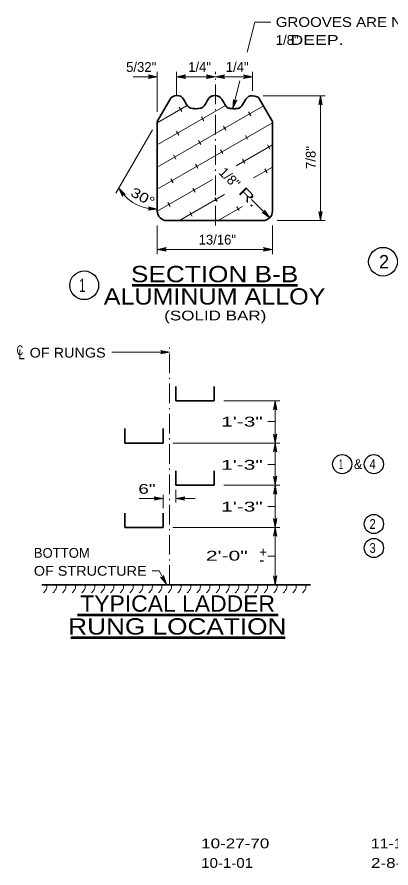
# Model space of a CAD drawing. Extents: x 16 to 133, y -56 to 112.
# Drawn here: x 16.4 to 55.4, y -51.9 to 36.9 of the extents above; entities that cross this region are included whole.
import ezdxf
from ezdxf.enums import TextEntityAlignment as Align

# ---------------------------------------------------------------- set-up
doc = ezdxf.new("R2010")
doc.units = 0
doc.header["$LTSCALE"] = 0.41
doc.linetypes.add('DOT_DASHED', pattern=[7.7, 5, -1.2, 0.3, -1.2])
for name, color, linetype, lineweight in [('1', 7, 'Continuous', 35), ('10', 7, 'Continuous', 13), ('12', 7, 'Continuous', 53), ('13', 7, 'Continuous', 25), ('6', 7, 'Continuous', 13)]:
    doc.layers.add(name, color=color, linetype=linetype, lineweight=lineweight)

msp = doc.modelspace()

# ---------------------------------------------------------------- linework, layer by layer
at = {"layer": '1'}
for p, q in [((31.0095, 25.9659), (32.4539, 28.4677)), ((43.0095, 25.9659), (41.5657, 28.4667)), ((31.0095, 25.9659), (31.0095, 16.6326)), ((43.0095, 16.6326), (43.0095, 25.9659)), ((32.0095, 15.6326), (42.0095, 15.6326)), ((32.9448, -3.1687), (32.9448, -1.6687)), ((36.9448, -3.1687), (36.9448, -1.6687)), ((32.9448, -3.1687), (36.9448, -3.1687)), ((27.6115, -7.5687), (27.6115, -6.0687)), ((31.6115, -7.5687), (31.6115, -6.0687)), ((27.6115, -7.5687), (31.6115, -7.5687)), ((32.9448, -11.9687), (32.9448, -10.4687)), ((36.9448, -11.9687), (36.9448, -10.4687)), ((32.9448, -11.9687), (36.9448, -11.9687)), ((27.6115, -16.3687), (27.6115, -14.8687)), ((31.6115, -16.3687), (31.6115, -14.8687)), ((27.6115, -16.3687), (31.6115, -16.3687)), ((18.9686, -22.3687), (46.9686, -22.3687))]:
    msp.add_line(p, q, dxfattribs=at)
for centre, start, end in [((32.0095, 16.6326), 180, 270), ((42.0095, 16.6326), 270, 0)]:
    msp.add_arc(centre, 1, start, end, dxfattribs=at)
for points in [[(32.4379, 28.4576), (32.5856, 28.55), (33.4826, 28.5571), (34.4532, 27.37), (34.6601, 27.3272), (35.0233, 27.2992)], [(37.6093, 28.4576), (37.4615, 28.55), (36.5646, 28.5571), (35.5939, 27.37), (35.3384, 27.3253), (35.0233, 27.2992)], [(36.413, 28.4576), (36.5608, 28.55), (37.4577, 28.5571), (38.4284, 27.37), (38.5783, 27.3312), (39.0133, 27.2992)], [(41.5656, 28.4666), (41.4018, 28.55), (40.5048, 28.5571), (39.5342, 27.37), (39.4171, 27.336), (39.0133, 27.2992)]]:
    msp.add_spline(points, degree=3, dxfattribs=at)
at = {"layer": '10'}
for p, q in [((31.0095, 26.9659), (31.0095, 31.1415)), ((33.0246, 28.6541), (33.0246, 31.1415)), ((40.9393, 29.1615), (40.9393, 31.1415)), ((28.5095, 30.6415), (31.0095, 30.6415)), ((33.0246, 30.6415), (40.9393, 30.6415)), ((39.6202, 30.2011), (38.8935, 27.3247)), ((42.0421, 28.6415), (48.5095, 28.6415)), ((48.0095, 15.6326), (48.0095, 28.6415)), ((26.6995, 18.5007), (30.5095, 25.0999)), ((42.7166, 15.9255), (40.8158, 17.8263)), ((31.0095, 15.1326), (31.0095, 12.1326)), ((43.0095, 15.1326), (43.0095, 12.1326)), ((43.5095, 15.6326), (48.5095, 15.6326)), ((31.0095, 12.6326), (43.0095, 12.6326)), ((32.2782, 1.91), (26.2782, 1.91)), ((37.9448, -3.1687), (43.7782, -3.1687)), ((43.2782, -22.3687), (43.2782, -3.1687)), ((43.2782, -5.3199), (42.5282, -5.3199)), ((32.6115, -7.5687), (43.7782, -7.5687)), ((43.2782, -9.808), (42.5282, -9.808)), ((37.9448, -11.9687), (43.7782, -11.9687)), ((31.6115, -14.3687), (31.6115, -12.9627)), ((32.9498, -12.4687), (32.9498, -13.7627)), ((29.1115, -13.3628), (31.6115, -13.3628)), ((32.9498, -13.3628), (34.9498, -13.3628)), ((43.2782, -14.1796), (42.5282, -14.1796)), ((32.6115, -16.3687), (43.7782, -16.3687)), ((43.2782, -19.3672), (42.5282, -19.3672))]:
    msp.add_line(p, q, dxfattribs=at)
at = {"layer": '10', "linetype": 'DOT_DASHED'}
for p, q in [((37.0638, 15.1326), (37.0638, 31.1415)), ((32.2782, -22.3687), (32.2782, 2.6313))]:
    msp.add_line(p, q, dxfattribs=at)
at = {"layer": '10'}
for points in [[(42.8534, 36.3383), (41.1704, 36.3383), (40.3792, 33.206)], [(31.0095, 30.6415), (30.0775, 30.4667), (30.1493, 30.5165), (30.1863, 30.579), (30.197, 30.6415), (30.1863, 30.704), (30.1493, 30.7665), (30.0775, 30.8163), (31.0095, 30.6415), (30.1493, 30.7665), (30.1863, 30.704), (31.0095, 30.6415), (30.197, 30.6415), (30.1863, 30.579), (31.0095, 30.6415), (30.1493, 30.5165)], [(33.0246, 30.6415), (33.9567, 30.8163), (33.8849, 30.7665), (33.8478, 30.704), (33.8371, 30.6415), (33.8478, 30.579), (33.8849, 30.5165), (33.9567, 30.4667), (33.0246, 30.6415), (33.8849, 30.5165), (33.8478, 30.579), (33.0246, 30.6415), (33.8371, 30.6415), (33.8478, 30.704), (33.0246, 30.6415), (33.8849, 30.7665)], [(37.0638, 30.6415), (36.1317, 30.4667), (36.2036, 30.5165), (36.2406, 30.579), (36.2513, 30.6415), (36.2406, 30.704), (36.2036, 30.7665), (36.1317, 30.8163), (37.0638, 30.6415), (36.2036, 30.7665), (36.2406, 30.704), (37.0638, 30.6415), (36.2513, 30.6415), (36.2406, 30.579), (37.0638, 30.6415), (36.2036, 30.5165)], [(37.0638, 30.6415), (37.9959, 30.4667), (37.9241, 30.5165), (37.887, 30.579), (37.8763, 30.6415), (37.887, 30.704), (37.9241, 30.7665), (37.9959, 30.8163), (37.0638, 30.6415), (37.9241, 30.7665), (37.887, 30.704), (37.0638, 30.6415), (37.8763, 30.6415), (37.887, 30.579), (37.0638, 30.6415), (37.9241, 30.5165)], [(40.9393, 30.6415), (40.0072, 30.4667), (40.079, 30.5165), (40.1161, 30.579), (40.1268, 30.6415), (40.1161, 30.704), (40.079, 30.7665), (40.0072, 30.8163), (40.9393, 30.6415), (40.079, 30.7665), (40.1161, 30.704), (40.9393, 30.6415), (40.1268, 30.6415), (40.1161, 30.579), (40.9393, 30.6415), (40.079, 30.5165)], [(48.0095, 28.6415), (48.1843, 27.7094), (48.1345, 27.7813), (48.072, 27.8183), (48.0095, 27.829), (47.947, 27.8183), (47.8845, 27.7813), (47.8348, 27.7094), (48.0095, 28.6415), (47.8845, 27.7813), (47.947, 27.8183), (48.0095, 28.6415), (48.0095, 27.829), (48.072, 27.8183), (48.0095, 28.6415), (48.1345, 27.7813)], [(38.8935, 27.3247), (38.9524, 28.2712), (38.983, 28.1893), (39.0346, 28.1381), (39.0925, 28.1124), (39.1558, 28.1075), (39.2254, 28.1281), (39.2913, 28.1856), (38.8935, 27.3247), (39.2254, 28.1281), (39.1558, 28.1075), (38.8935, 27.3247), (39.0925, 28.1124), (39.0346, 28.1381), (38.8935, 27.3247), (38.983, 28.1893)], [(27.0007, 19.0261), (27.6747, 18.359), (27.5929, 18.3898), (27.5205, 18.3847), (27.463, 18.3579), (27.4176, 18.3135), (27.3873, 18.2475), (27.3873, 18.1601), (27.0007, 19.0261), (27.3873, 18.2475), (27.4176, 18.3135), (27.0007, 19.0261), (27.463, 18.3579), (27.5205, 18.3847), (27.0007, 19.0261), (27.5929, 18.3898)], [(31.0095, 16.8172), (30.0683, 16.7017), (30.1431, 16.7468), (30.184, 16.8068), (30.1987, 16.8685), (30.1919, 16.9316), (30.1589, 16.9963), (30.0904, 17.0505), (31.0095, 16.8172), (30.1589, 16.9963), (30.1919, 16.9316), (31.0095, 16.8172), (30.1987, 16.8685), (30.184, 16.8068), (31.0095, 16.8172), (30.1431, 16.7468)], [(42.7166, 15.9255), (41.934, 16.461), (42.02, 16.4454), (42.0903, 16.4634), (42.1421, 16.5), (42.1787, 16.5518), (42.1967, 16.6221), (42.1811, 16.7081), (42.7166, 15.9255), (42.1967, 16.6221), (42.1787, 16.5518), (42.7166, 15.9255), (42.1421, 16.5), (42.0903, 16.4634), (42.7166, 15.9255), (42.02, 16.4454)], [(48.0095, 15.6326), (47.8348, 16.5646), (47.8845, 16.4928), (47.947, 16.4558), (48.0095, 16.4451), (48.072, 16.4558), (48.1345, 16.4928), (48.1843, 16.5646), (48.0095, 15.6326), (48.1345, 16.4928), (48.072, 16.4558), (48.0095, 15.6326), (48.0095, 16.4451), (47.947, 16.4558), (48.0095, 15.6326), (47.8845, 16.4928)], [(31.0095, 12.6326), (31.9416, 12.8073), (31.8698, 12.7576), (31.8327, 12.6951), (31.822, 12.6326), (31.8327, 12.5701), (31.8698, 12.5076), (31.9416, 12.4578), (31.0095, 12.6326), (31.8698, 12.5076), (31.8327, 12.5701), (31.0095, 12.6326), (31.822, 12.6326), (31.8327, 12.6951), (31.0095, 12.6326), (31.8698, 12.7576)], [(43.0095, 12.6326), (42.0775, 12.4578), (42.1493, 12.5076), (42.1863, 12.5701), (42.197, 12.6326), (42.1863, 12.6951), (42.1493, 12.7576), (42.0775, 12.8073), (43.0095, 12.6326), (42.1493, 12.7576), (42.1863, 12.6951), (43.0095, 12.6326), (42.197, 12.6326), (42.1863, 12.5701), (43.0095, 12.6326), (42.1493, 12.5076)], [(32.2782, 1.91), (31.3461, 1.7352), (31.4179, 1.785), (31.4549, 1.8475), (31.4657, 1.91), (31.4549, 1.9725), (31.4179, 2.035), (31.3461, 2.0848), (32.2782, 1.91), (31.4179, 2.035), (31.4549, 1.9725), (32.2782, 1.91), (31.4657, 1.91), (31.4549, 1.8475), (32.2782, 1.91), (31.4179, 1.785)], [(43.2782, -3.1687), (43.4529, -4.1007), (43.4032, -4.0289), (43.3407, -3.9919), (43.2782, -3.9812), (43.2157, -3.9919), (43.1532, -4.0289), (43.1034, -4.1007), (43.2782, -3.1687), (43.1532, -4.0289), (43.2157, -3.9919), (43.2782, -3.1687), (43.2782, -3.9812), (43.3407, -3.9919), (43.2782, -3.1687), (43.4032, -4.0289)], [(43.2782, -7.5687), (43.4529, -6.6366), (43.4032, -6.7084), (43.3407, -6.7454), (43.2782, -6.7562), (43.2157, -6.7454), (43.1532, -6.7084), (43.1034, -6.6366), (43.2782, -7.5687), (43.1532, -6.7084), (43.2157, -6.7454), (43.2782, -7.5687), (43.2782, -6.7562), (43.3407, -6.7454), (43.2782, -7.5687), (43.4032, -6.7084)], [(43.2782, -7.5687), (43.4529, -8.5007), (43.4032, -8.4289), (43.3407, -8.3919), (43.2782, -8.3812), (43.2157, -8.3919), (43.1532, -8.4289), (43.1034, -8.5007), (43.2782, -7.5687), (43.1532, -8.4289), (43.2157, -8.3919), (43.2782, -7.5687), (43.2782, -8.3812), (43.3407, -8.3919), (43.2782, -7.5687), (43.4032, -8.4289)], [(43.2782, -11.9687), (43.4529, -11.0366), (43.4032, -11.1084), (43.3407, -11.1454), (43.2782, -11.1562), (43.2157, -11.1454), (43.1532, -11.1084), (43.1034, -11.0366), (43.2782, -11.9687), (43.1532, -11.1084), (43.2157, -11.1454), (43.2782, -11.9687), (43.2782, -11.1562), (43.3407, -11.1454), (43.2782, -11.9687), (43.4032, -11.1084)], [(43.2782, -11.9687), (43.4529, -12.9007), (43.4032, -12.8289), (43.3407, -12.7919), (43.2782, -12.7812), (43.2157, -12.7919), (43.1532, -12.8289), (43.1034, -12.9007), (43.2782, -11.9687), (43.1532, -12.8289), (43.2157, -12.7919), (43.2782, -11.9687), (43.2782, -12.7812), (43.3407, -12.7919), (43.2782, -11.9687), (43.4032, -12.8289)], [(31.6115, -13.3628), (30.6794, -13.5375), (30.7512, -13.4878), (30.7883, -13.4253), (30.799, -13.3628), (30.7883, -13.3003), (30.7512, -13.2378), (30.6794, -13.188), (31.6115, -13.3628), (30.7512, -13.2378), (30.7883, -13.3003), (31.6115, -13.3628), (30.799, -13.3628), (30.7883, -13.4253), (31.6115, -13.3628), (30.7512, -13.4878)], [(32.9498, -13.3628), (33.8819, -13.188), (33.8101, -13.2378), (33.7731, -13.3003), (33.7623, -13.3628), (33.7731, -13.4253), (33.8101, -13.4878), (33.8819, -13.5375), (32.9498, -13.3628), (33.8101, -13.4878), (33.7731, -13.4253), (32.9498, -13.3628), (33.7623, -13.3628), (33.7731, -13.3003), (32.9498, -13.3628), (33.8101, -13.2378)], [(43.2782, -16.3687), (43.4529, -15.4366), (43.4032, -15.5084), (43.3407, -15.5454), (43.2782, -15.5562), (43.2157, -15.5454), (43.1532, -15.5084), (43.1034, -15.4366), (43.2782, -16.3687), (43.1532, -15.5084), (43.2157, -15.5454), (43.2782, -16.3687), (43.2782, -15.5562), (43.3407, -15.5454), (43.2782, -16.3687), (43.4032, -15.5084)], [(43.2782, -16.3687), (43.4529, -17.3007), (43.4032, -17.2289), (43.3407, -17.1919), (43.2782, -17.1812), (43.2157, -17.1919), (43.1532, -17.2289), (43.1034, -17.3007), (43.2782, -16.3687), (43.1532, -17.2289), (43.2157, -17.1919), (43.2782, -16.3687), (43.2782, -17.1812), (43.3407, -17.1919), (43.2782, -16.3687), (43.4032, -17.2289)], [(30.471, -20.9), (31.1921, -20.9), (31.9612, -22.2949)], [(31.9612, -22.2949), (31.3581, -21.563), (31.4364, -21.6019), (31.509, -21.6042), (31.5689, -21.5834), (31.6185, -21.5438), (31.6553, -21.4812), (31.6642, -21.3943), (31.9612, -22.2949), (31.6553, -21.4812), (31.6185, -21.5438), (31.9612, -22.2949), (31.5689, -21.5834), (31.509, -21.6042), (31.9612, -22.2949), (31.4364, -21.6019)], [(43.2782, -22.3687), (43.1034, -21.4366), (43.1532, -21.5084), (43.2157, -21.5454), (43.2782, -21.5562), (43.3407, -21.5454), (43.4032, -21.5084), (43.4529, -21.4366), (43.2782, -22.3687), (43.4032, -21.5084), (43.3407, -21.5454), (43.2782, -22.3687), (43.2782, -21.5562), (43.2157, -21.5454), (43.2782, -22.3687), (43.1532, -21.5084)]]:
    msp.add_lwpolyline(points, dxfattribs=at)
msp.add_arc((30.8826, 21.3154), 4.5, 210.50913, 271.61683, dxfattribs=at)
at = {"layer": '12'}
for p, q in [((28.3976, 8.8847), (45.6215, 8.8847)), ((22.6817, -25.4759), (43.6093, -25.4759)), ((22.0066, -27.863), (44.3458, -27.863))]:
    msp.add_line(p, q, dxfattribs=at)
at = {"layer": '13'}
for centre, radius in [((54.5317, 11.3401), 1.5), ((23.3976, 8.8847), 1.5), ((50.2769, -9.7702), 1), ((53.5721, -9.7702), 1), ((53.5721, -16.0143), 1), ((53.5721, -18.5184), 1)]:
    msp.add_circle(centre, radius, dxfattribs=at)
at = {"layer": '6'}
for p, q in [((31.0095, 25.8367), (34.1251, 27.6355)), ((31.0095, 23.5273), (38.1168, 27.6307)), ((31.0095, 21.2179), (42.0654, 27.6011)), ((33.551, 27.0154), (33.301, 27.4484)), ((40.7471, 26.5512), (40.4971, 26.9842)), ((31.0095, 18.9085), (43.0095, 25.8367)), ((35.85, 26.0333), (35.6, 26.4663)), ((33.2519, 24.5333), (33.0019, 24.9663)), ((38.149, 25.0513), (37.899, 25.4843)), ((35.551, 23.5513), (35.301, 23.9843)), ((40.4211, 24.1159), (40.1981, 24.5022)), ((39.2275, 21.3438), (43.0095, 23.5273)), ((42.7471, 23.0871), (42.4971, 23.5202)), ((32.9529, 22.0513), (32.7029, 22.4843)), ((37.8231, 22.6159), (37.6, 23.0022)), ((35.225, 21.1159), (35.0019, 21.5022)), ((40.1221, 21.6338), (39.899, 22.0201)), ((41.0463, 20.0844), (43.0095, 21.2179)), ((42.4481, 20.6051), (42.1981, 21.0381)), ((31.0095, 16.5991), (36.7737, 19.9271)), ((32.6539, 19.5692), (32.4039, 20.0022)), ((34.9529, 18.5872), (34.7029, 19.0202)), ((33.3354, 15.6326), (38.0242, 18.3396)), ((37.2519, 17.6051), (37.0019, 18.0381)), ((32.3548, 17.0872), (32.1048, 17.5202)), ((37.3354, 15.6326), (39.8723, 17.0973)), ((39.524, 16.6697), (39.301, 17.0561)), ((34.6539, 16.1051), (34.4039, 16.5381))]:
    msp.add_line(p, q, dxfattribs=at)
for points in [[(19.4766, -22.3385), (19.4766, -22.7136), (19.1358, -23.191)], [(20.4766, -22.3385), (20.4766, -22.7136), (20.1358, -23.191)], [(21.4766, -22.3385), (21.4766, -22.7136), (21.1358, -23.191)], [(22.4766, -22.3385), (22.4766, -22.7136), (22.1358, -23.191)], [(23.4766, -22.3385), (23.4766, -22.7136), (23.1358, -23.191)], [(24.4766, -22.3385), (24.4766, -22.7136), (24.1358, -23.191)], [(25.4766, -22.3385), (25.4766, -22.7136), (25.1358, -23.191)], [(26.4766, -22.3385), (26.4766, -22.7136), (26.1358, -23.191)], [(27.4766, -22.3385), (27.4766, -22.7136), (27.1358, -23.191)], [(28.4766, -22.3385), (28.4766, -22.7136), (28.1358, -23.191)], [(29.4766, -22.3385), (29.4766, -22.7136), (29.1358, -23.191)], [(30.4766, -22.3385), (30.4766, -22.7136), (30.1358, -23.191)], [(31.4766, -22.3385), (31.4766, -22.7136), (31.1358, -23.191)], [(32.4766, -22.3385), (32.4766, -22.7136), (32.1358, -23.191)], [(33.4766, -22.3385), (33.4766, -22.7136), (33.1358, -23.191)], [(34.4766, -22.3385), (34.4766, -22.7136), (34.1358, -23.191)], [(35.4766, -22.3385), (35.4766, -22.7136), (35.1358, -23.191)], [(36.4766, -22.3385), (36.4766, -22.7136), (36.1358, -23.191)], [(37.4766, -22.3385), (37.4766, -22.7136), (37.1358, -23.191)], [(38.4766, -22.3385), (38.4766, -22.7136), (38.1358, -23.191)], [(39.4766, -22.3385), (39.4766, -22.7136), (39.1358, -23.191)], [(40.4766, -22.3385), (40.4766, -22.7136), (40.1358, -23.191)], [(41.4766, -22.3385), (41.4766, -22.7136), (41.1358, -23.191)], [(42.4766, -22.3385), (42.4766, -22.7136), (42.1358, -23.191)], [(43.4766, -22.3385), (43.4766, -22.7136), (43.1358, -23.191)], [(44.4766, -22.3385), (44.4766, -22.7136), (44.1358, -23.191)], [(45.4766, -22.3385), (45.4766, -22.7136), (45.1358, -23.191)], [(46.4766, -22.3385), (46.4766, -22.7136), (46.1358, -23.191)]]:
    msp.add_spline(points, degree=3, dxfattribs=at)

# ---------------------------------------------------------------- texts
at = {"layer": '12'}
for s, width, p in [('GROOVES ARE NOT TO EXCEED', 1.15, (43.3534, 35.8283)), ('   DEEP.', 1.35, (43.3534, 33.9583)), ('OF RUNGS', 1.1, (17.7106, 1.3414)), ('OF STRUCTURE', 1.1, (18.1402, -21.41)), ('-', 1.15, (41.646, -20.2716))]:
    msp.add_text(s, height=1.02, dxfattribs=dict(at, width=width)).set_placement(p)
at = {"layer": '12', "width": 1.65}
msp.add_text('R.', height=1.02, rotation=315, dxfattribs=at).set_placement((39.3945, 18.5263))
at = {"layer": '12'}
for s, height, width, p in [('SECTION B-B', 1.7, 1.2, (36.9777, 9.2009)), ('ALUMINUM ALLOY', 1.7, 1.15, (36.9777, 6.8685)), ('(SOLID BAR)', 1.02, 1.3, (37.0494, 5.2178)), ('C', 1.02, 0.7, (16.6901, 1.6014)), ('L', 1.02, 0.85, (16.8675, 1.1761)), ('TYPICAL LADDER', 1.7, 1.05, (33.1268, -25.1597)), ('RUNG LOCATION', 1.7, 1.2, (33.0927, -27.5468))]:
    msp.add_text(s, height=height, dxfattribs=dict(at, width=width)).set_placement(p, align=Align.CENTER)
for s, p in [('BOTTOM', (18.1402, -19.54)), ('+', (41.6348, -19.4368))]:
    msp.add_text(s, height=1.02, dxfattribs=at).set_placement(p)
at = {"layer": '13'}
msp.add_text('1/8"', height=1.02, dxfattribs=at).set_placement((43.3534, 33.9583))
for s, height, p in [('5/32"', 1.02, (29.3312, 31.1415)), ('1/4"', 1.02, (35.4175, 31.1415)), ('1/4"', 1.02, (39.3312, 31.1415)), ('13/16"', 1.02, (37.266, 13.1326)), ('2', 1.4, (54.6301, 10.6401))]:
    msp.add_text(s, height=height, dxfattribs=at).set_placement(p, align=Align.CENTER)
for s, rotation, p in [('7/8"', 90, (47.5095, 22.2087)), ('1/8"', 315, (38.1869, 19.734))]:
    msp.add_text(s, height=1.02, rotation=rotation, dxfattribs=at).set_placement(p, align=Align.CENTER)
at = {"layer": '13', "width": 1.25}
msp.add_text('30°', height=1.02, rotation=331.063, dxfattribs=at).set_placement((29.2566, 17.6437), align=Align.CENTER)
at = {"layer": '13'}
for s, height, width, p in [('1', 1.4, 0.65, (23.1992, 8.1847)), ('1\'-3"', 1.02, 1.6, (39.8281, -5.8483)), ('1\'-3"', 1.02, 1.6, (39.8281, -10.3515)), ('1', 1.02, 0.55, (50.1486, -10.2802)), ('&', 1.02, 0.95, (51.932, -10.2802)), ('4', 1.02, 0.85, (53.4437, -10.2802)), ('6"', 1.02, 1.45, (29.9332, -12.8628)), ('1\'-3"', 1.02, 1.6, (39.8281, -14.7139)), ('2', 1.02, 0.85, (53.4437, -16.5243)), ('3', 1.02, 0.85, (53.4437, -19.0284)), ('2\'-0"', 1.02, 1.6, (38.25, -19.8308))]:
    msp.add_text(s, height=height, dxfattribs=dict(at, width=width)).set_placement(p, align=Align.CENTER)
for s, width, p in [('10-27-70', 1.3, (35.5816, -49.8382)), ('11-19-70', 1.2, (53.2707, -49.8382)), ('10-1-01', 1.15, (35.5816, -51.8783)), ('2-8-83', 1.3, (53.2707, -51.8783))]:
    msp.add_text(s, height=1.02, dxfattribs=dict(at, width=width)).set_placement(p)

doc.saveas('drawing.dxf')
